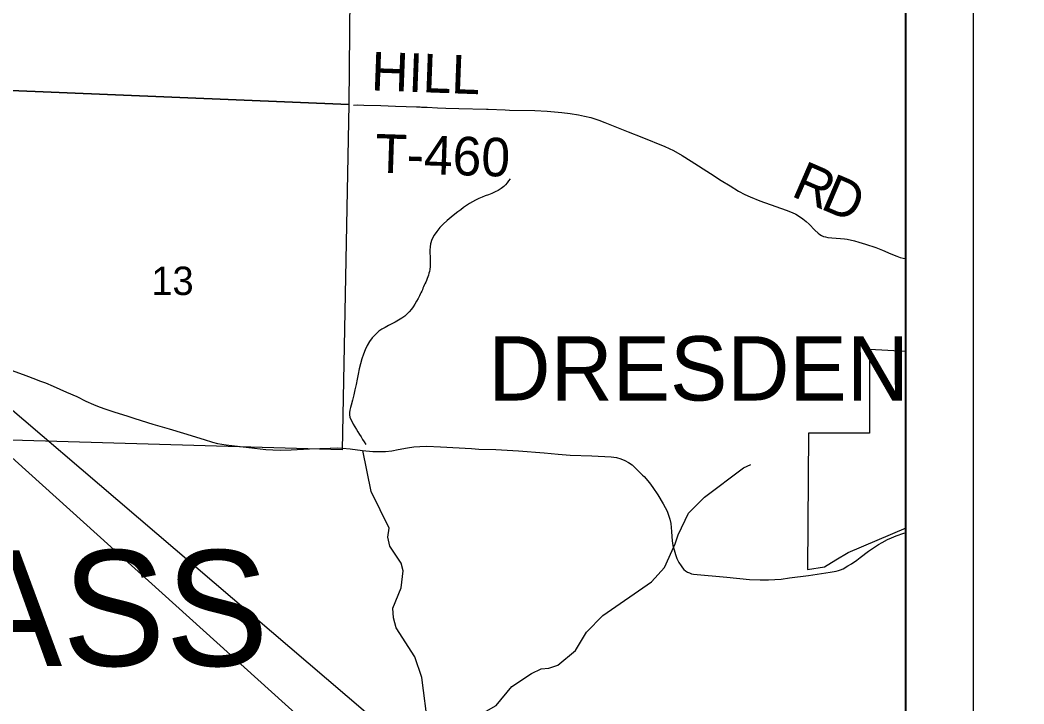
# Model space of a CAD drawing. Extents: x 0 to 34, y 0 to 22.
# Drawn here: x 8.096 to 9.575, y 18.295 to 19.303 of the extents above; entities that cross this region are included whole.
import ezdxf

# ---------------------------------------------------------------- set-up
doc = ezdxf.new("R2010")
doc.units = 0
for name, color, linetype in [('GM_X_Corporation', 7, 'Continuous'), ('GM_X_Corporation_Text', 7, 'Continuous'), ('GM_X_County', 7, 'Continuous'), ('GM_X_Minor_River', 7, 'Continuous'), ('GM_X_Section', 7, 'Continuous'), ('GM_X_Section_Text', 7, 'Continuous'), ('GM_X_Township', 7, 'Continuous'), ('GM_X_Township_Road', 7, 'Continuous'), ('GM_X_Township_Road_Text', 7, 'Continuous'), ('GM_X_Township_Text', 7, 'Continuous'), ('SH_Data', 7, 'Continuous')]:
    doc.layers.add(name, color=color, linetype=linetype)

msp = doc.modelspace()

# ---------------------------------------------------------------- linework, layer by layer
at = {"layer": 'GM_X_Corporation'}
msp.add_line((9.4013, 18.5545), (9.4013, 18.8144), dxfattribs=at)
msp.add_lwpolyline([(9.4013, 18.8144), (9.3473, 18.8172), (9.3473, 18.6941), (9.2573, 18.6941), (9.256, 18.4933), (9.2809, 18.4972), (9.2975, 18.5077), (9.3161, 18.5184), (9.4013, 18.5545)], dxfattribs=at)
at = {"layer": 'GM_X_County'}
msp.add_lwpolyline([(7.0736, 21.2003), (2.6013, 21.2003), (2.6013, 14.4003), (9.4013, 14.4003), (9.4013, 21.1598)], dxfattribs=at)
at = {"layer": 'GM_X_Minor_River'}
for points in [[(8.6975, 18.2613), (8.688, 18.3341), (8.6776, 18.3644), (8.6502, 18.4072), (8.6463, 18.422), (8.6451, 18.4364), (8.6578, 18.4664), (8.6604, 18.4911), (8.6577, 18.5024), (8.6409, 18.5278), (8.6378, 18.5407), (8.64, 18.554), (8.6132, 18.6081), (8.6012, 18.6684)], [(8.6808, 18.2367), (8.6953, 18.228), (8.7713, 18.2784), (8.7977, 18.2929), (8.8207, 18.3207), (8.8495, 18.3402), (8.8638, 18.3467), (8.8752, 18.3479), (8.8881, 18.3521), (8.9145, 18.3738), (8.9303, 18.4008), (8.9544, 18.4256), (9.0262, 18.4749), (9.0455, 18.4962), (9.0612, 18.5312), (9.0657, 18.5441), (9.0807, 18.576), (9.1045, 18.5996), (9.1615, 18.6431), (9.1725, 18.6477)]]:
    msp.add_lwpolyline(points, dxfattribs=at)
msp.add_spline([(8.818, 19.0686), (8.8086, 19.0576), (8.7719, 19.0396), (8.7368, 19.0167), (8.701, 18.973), (8.6997, 18.935), (8.6926, 18.9141), (8.6847, 18.8966), (8.6629, 18.8666), (8.6248, 18.8441), (8.584, 18.7354), (8.5814, 18.721), (8.5871, 18.7074), (8.6054, 18.6775)], degree=3, dxfattribs=at)
at = {"layer": 'GM_X_Section'}
for points in [[(8.0858, 20.1828), (8.5906, 20.172), (8.5904, 20.1552), (8.5847, 19.6569), (8.5803, 19.1784), (8.0709, 19.1994)], [(8.0709, 19.1994), (8.5803, 19.1784), (8.5708, 18.6694), (8.083, 18.6836), (8.0639, 18.6844)]]:
    msp.add_lwpolyline(points, close=True, dxfattribs=at)
at = {"layer": 'GM_X_Township'}
msp.add_line((9.4013, 16.1226), (9.4013, 21.1598), dxfattribs=at)
at = {"layer": 'GM_X_Township_Road'}
for points in [[(8.5873, 19.1775), (8.5935, 19.1776), (8.6028, 19.1774), (8.6276, 19.1767), (8.6494, 19.176), (8.6649, 19.1755), (8.6804, 19.1749), (8.6855, 19.1747)], [(8.6855, 19.1747), (8.6874, 19.1745), (8.6958, 19.1741), (8.7112, 19.1733), (8.7236, 19.1729), (8.7423, 19.1724), (8.7834, 19.1712)], [(8.7834, 19.1712), (8.7857, 19.1712), (8.8105, 19.1702), (8.8173, 19.17)], [(8.8173, 19.17), (8.8545, 19.1693), (8.8726, 19.1683), (8.8942, 19.1666), (8.9065, 19.1652), (8.9188, 19.1632), (8.9278, 19.1613), (8.9368, 19.1589), (8.9486, 19.1552), (8.9574, 19.1519), (8.9919, 19.138), (9.0122, 19.1301), (9.0461, 19.1164), (9.0523, 19.1135), (9.0587, 19.1103), (9.0713, 19.103), (9.0846, 19.095), (9.1133, 19.0765), (9.1287, 19.0665), (9.142, 19.0584), (9.1546, 19.0507), (9.1635, 19.0459), (9.1715, 19.0423), (9.186, 19.0363), (9.2095, 19.0282), (9.2248, 19.0228), (9.2333, 19.0192), (9.2389, 19.0165), (9.2442, 19.0134), (9.2493, 19.0099), (9.2541, 19.0061), (9.2586, 19.0019), (9.267, 18.993), (9.2715, 18.9887), (9.274, 18.9868), (9.2768, 18.9853), (9.2796, 18.984), (9.2826, 18.9831), (9.2857, 18.9824), (9.2919, 18.9817), (9.3044, 18.9811), (9.3105, 18.9805), (9.3145, 18.9799), (9.325, 18.9774), (9.3315, 18.9755), (9.3415, 18.9725), (9.3566, 18.9677), (9.3664, 18.9638), (9.3786, 18.9585), (9.3876, 18.9548), (9.3924, 18.9529), (9.3968, 18.952), (9.4003, 18.9516), (9.4013, 18.9515)], [(8.0846, 18.7863), (8.1049, 18.7788), (8.1193, 18.7734), (8.125, 18.7713), (8.1336, 18.768), (8.145, 18.7634), (8.1646, 18.7547), (8.1799, 18.7482), (8.1933, 18.7413), (8.2043, 18.7362), (8.2127, 18.7328), (8.2228, 18.7292), (8.2359, 18.7249), (8.2537, 18.7195), (8.2655, 18.7158), (8.2921, 18.7072), (8.316, 18.7004), (8.3368, 18.694), (8.3675, 18.6846), (8.3797, 18.6808), (8.3869, 18.6791), (8.3997, 18.6769), (8.4417, 18.6721), (8.4585, 18.6702), (8.4685, 18.6695), (8.4798, 18.6689), (8.4954, 18.6697), (8.5227, 18.671), (8.5532, 18.6721), (8.5636, 18.6724), (8.571, 18.6719), (8.5825, 18.6709), (8.6005, 18.6685), (8.6159, 18.6671), (8.6259, 18.6671), (8.6343, 18.6673), (8.6439, 18.6683), (8.6533, 18.6698), (8.667, 18.6727), (8.6763, 18.6741), (8.6852, 18.6746), (8.6953, 18.6748), (8.7157, 18.6739), (8.7613, 18.6715), (8.7718, 18.6707), (8.7968, 18.6698), (8.8306, 18.6681), (8.8682, 18.6652), (8.8886, 18.6633), (8.9067, 18.6619), (8.9386, 18.6609), (8.9669, 18.6592), (8.9745, 18.6582), (8.9813, 18.6565), (8.9868, 18.654), (8.9926, 18.6508), (8.9976, 18.6472), (9.0022, 18.6429), (9.0132, 18.6323), (9.0152, 18.6301), (9.0231, 18.6208), (9.0283, 18.6141), (9.0358, 18.6031), (9.0436, 18.5899), (9.0466, 18.5845), (9.0493, 18.579), (9.0515, 18.5733), (9.0533, 18.5675), (9.0545, 18.561), (9.0559, 18.5491), (9.0564, 18.5417), (9.0568, 18.5356), (9.0579, 18.5288), (9.0594, 18.522), (9.0615, 18.5153), (9.0636, 18.5096), (9.0663, 18.5035), (9.0697, 18.4985), (9.0719, 18.4958), (9.074, 18.4934), (9.0764, 18.4913), (9.0791, 18.4895), (9.082, 18.4881), (9.0851, 18.4871), (9.0882, 18.4864), (9.1373, 18.4821), (9.1707, 18.4787), (9.1865, 18.4782), (9.1987, 18.4782), (9.208, 18.4783), (9.2173, 18.4791), (9.2297, 18.4808), (9.2576, 18.4846), (9.2894, 18.4893), (9.2953, 18.4901), (9.2984, 18.4908), (9.3014, 18.4917), (9.3046, 18.4927), (9.3084, 18.4943), (9.3155, 18.4984), (9.3208, 18.5018), (9.3284, 18.5071), (9.3334, 18.5108), (9.3457, 18.5201), (9.353, 18.5254), (9.3605, 18.5301), (9.3658, 18.5331), (9.374, 18.5375), (9.3795, 18.54), (9.3867, 18.5429), (9.398, 18.5466), (9.4013, 18.5476)]]:
    msp.add_lwpolyline(points, dxfattribs=at)
at = {"layer": 'SH_Data'}
for p, q in [((9.5, 21.2997), (9.5, 14.2997)), ((9.4, 21.1997), (9.4, 14.3997))]:
    msp.add_line(p, q, dxfattribs=at)
msp.add_lwpolyline([(6.619, 19.9811), (10.5909, 16.3957), (10.5909, 16.5853)], close=True, dxfattribs=at)

# ---------------------------------------------------------------- texts
at = {"layer": 'GM_X_Corporation_Text'}
msp.add_text('DRESDEN', height=0.0947, rotation=0, dxfattribs=at).set_placement((8.7861, 18.7422))
at = {"layer": 'GM_X_Section_Text'}
msp.add_text('13', height=0.04186, rotation=0, dxfattribs=at).set_placement((8.2897, 18.8976))
at = {"layer": 'GM_X_Township_Road_Text'}
for s, height, rotation, p in [('HILL', 0.05682, 357.8891, (8.6126, 19.1992)), ('T-460', 0.05682, 358.1276, (8.6187, 19.0782)), ('R', 0.0568, 336.4944, (9.2303, 19.0441)), ('D', 0.0568, 336.9391, (9.2735, 19.0253))]:
    msp.add_text(s, height=height, rotation=rotation, dxfattribs=at).set_placement(p)
at = {"layer": 'GM_X_Township_Text'}
msp.add_text('CASS', height=0.17045, rotation=0, dxfattribs=at).set_placement((7.8418, 18.3512))

doc.saveas('drawing.dxf')
